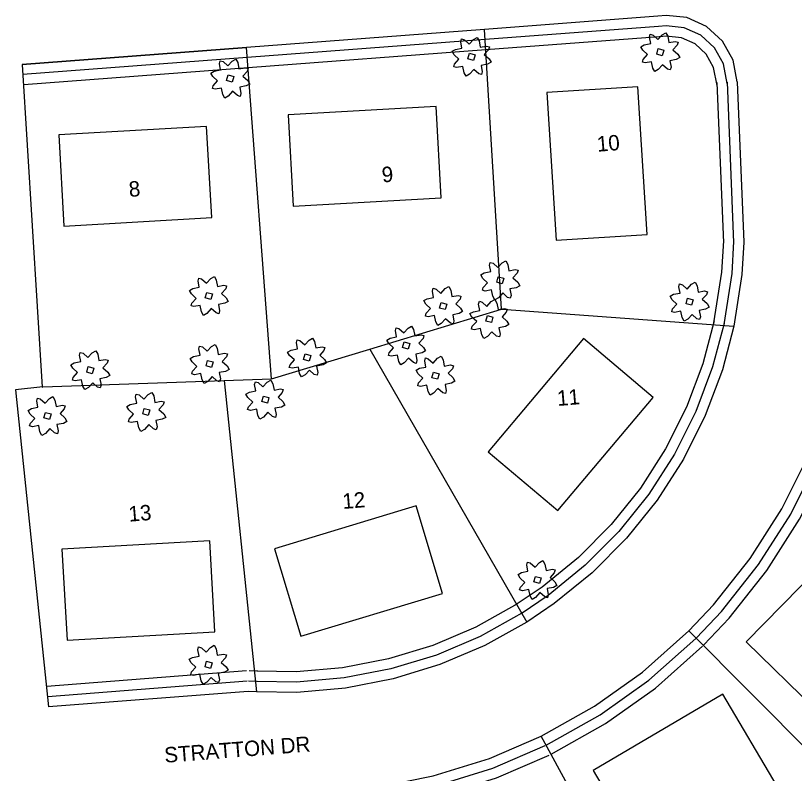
# Model space of a CAD drawing. Extents: x 1810019 to 1811399, y 1074962 to 1076105.
# Drawn here: x 1810244.4 to 1810548, y 1075531.7 to 1075827.1 of the extents above; entities that cross this region are included whole.
import ezdxf

# ---------------------------------------------------------------- set-up
doc = ezdxf.new("R2010")
doc.units = 0
for name, color, linetype in [('Environmental-New trees', 7, 'Continuous'), ('Property-Buildings', 7, 'Continuous'), ('Roadway-Land lines', 7, 'Continuous'), ('Roadway-Sidewalks', 7, 'Continuous'), ('Text-Property owner', 7, 'Continuous'), ('Text-Route label', 7, 'Continuous')]:
    doc.layers.add(name, color=color, linetype=linetype)

msp = doc.modelspace()

# ---------------------------------------------------------------- linework, layer by layer
at = {"layer": 'Environmental-New trees'}
for points in [[(1810488.71, 1075808.93), (1810489.02, 1075810.01), (1810490.71, 1075811.87), (1810488.85, 1075813.57), (1810488.07, 1075814.95), (1810489.43, 1075815.71), (1810491.93, 1075816.21), (1810491.46, 1075818.68), (1810491.76, 1075819.76), (1810492.85, 1075819.45), (1810494.71, 1075817.76), (1810496.4, 1075819.62), (1810497.79, 1075820.4), (1810498.57, 1075819.01), (1810499.04, 1075816.54), (1810501.51, 1075817.01), (1810502.6, 1075816.71), (1810502.23, 1075815.55), (1810500.6, 1075813.76), (1810502.46, 1075812.07), (1810503.24, 1075810.68), (1810501.88, 1075809.92), (1810499.38, 1075809.43), (1810499.85, 1075806.96), (1810499.54, 1075805.88), (1810498.46, 1075806.18), (1810496.6, 1075807.88), (1810494.91, 1075806.01), (1810493.52, 1075805.24), (1810492.74, 1075806.63), (1810492.27, 1075809.1), (1810489.8, 1075808.62)], [(1810415.17, 1075807.11), (1810415.47, 1075808.19), (1810417.16, 1075810.05), (1810415.3, 1075811.75), (1810414.52, 1075813.14), (1810415.88, 1075813.89), (1810418.38, 1075814.39), (1810417.91, 1075816.86), (1810418.22, 1075817.94), (1810419.3, 1075817.64), (1810421.16, 1075815.94), (1810422.85, 1075817.8), (1810424.24, 1075818.58), (1810425.02, 1075817.19), (1810425.49, 1075814.72), (1810427.96, 1075815.19), (1810429.05, 1075814.89), (1810428.68, 1075813.73), (1810427.05, 1075811.95), (1810428.91, 1075810.25), (1810429.69, 1075808.86), (1810428.34, 1075808.11), (1810425.83, 1075807.61), (1810426.3, 1075805.14), (1810426, 1075804.06), (1810424.91, 1075804.36), (1810423.05, 1075806.06), (1810421.36, 1075804.2), (1810419.97, 1075803.42), (1810419.19, 1075804.81), (1810418.72, 1075807.28), (1810416.25, 1075806.8)], [(1810494.88, 1075814.21), (1810497.04, 1075813.6), (1810496.43, 1075811.43), (1810494.27, 1075812.04)], [(1810321.09, 1075798.64), (1810321.4, 1075799.72), (1810323.09, 1075801.58), (1810321.23, 1075803.27), (1810320.45, 1075804.66), (1810321.81, 1075805.42), (1810324.31, 1075805.91), (1810323.84, 1075808.38), (1810324.15, 1075809.47), (1810325.23, 1075809.16), (1810327.09, 1075807.47), (1810328.78, 1075809.33), (1810330.17, 1075810.11), (1810330.95, 1075808.72), (1810331.42, 1075806.25), (1810333.89, 1075806.72), (1810334.98, 1075806.42), (1810334.61, 1075805.26), (1810332.98, 1075803.47), (1810334.84, 1075801.78), (1810335.62, 1075800.39), (1810334.27, 1075799.63), (1810331.76, 1075799.14), (1810332.23, 1075796.67), (1810331.93, 1075795.59), (1810330.84, 1075795.89), (1810328.98, 1075797.58), (1810327.29, 1075795.72), (1810325.9, 1075794.94), (1810325.12, 1075796.33), (1810324.65, 1075798.8), (1810322.18, 1075798.33)], [(1810421.33, 1075812.39), (1810423.49, 1075811.78), (1810422.88, 1075809.61), (1810420.72, 1075810.22)], [(1810327.26, 1075803.91), (1810329.42, 1075803.3), (1810328.81, 1075801.14), (1810326.65, 1075801.75)], [(1810426.37, 1075720.01), (1810426.67, 1075721.09), (1810428.37, 1075722.96), (1810426.5, 1075724.65), (1810425.73, 1075726.04), (1810427.08, 1075726.79), (1810429.59, 1075727.29), (1810429.11, 1075729.76), (1810429.42, 1075730.84), (1810430.5, 1075730.54), (1810432.36, 1075728.84), (1810434.06, 1075730.7), (1810435.44, 1075731.48), (1810436.22, 1075730.09), (1810436.7, 1075727.62), (1810439.17, 1075728.1), (1810440.25, 1075727.79), (1810439.88, 1075726.63), (1810438.25, 1075724.85), (1810440.11, 1075723.15), (1810440.89, 1075721.76), (1810439.54, 1075721.01), (1810437.03, 1075720.51), (1810437.5, 1075718.04), (1810437.2, 1075716.96), (1810436.12, 1075717.26), (1810434.25, 1075718.96), (1810432.56, 1075717.1), (1810431.17, 1075716.32), (1810430.39, 1075717.71), (1810429.92, 1075720.18), (1810427.45, 1075719.71)], [(1810312.77, 1075713.93), (1810313.07, 1075715.01), (1810314.77, 1075716.87), (1810312.91, 1075718.57), (1810312.13, 1075719.96), (1810313.48, 1075720.71), (1810315.99, 1075721.21), (1810315.52, 1075723.68), (1810315.82, 1075724.76), (1810316.9, 1075724.46), (1810318.77, 1075722.76), (1810320.46, 1075724.62), (1810321.85, 1075725.4), (1810322.62, 1075724.01), (1810323.1, 1075721.54), (1810325.57, 1075722.02), (1810326.65, 1075721.71), (1810326.28, 1075720.55), (1810324.65, 1075718.77), (1810326.51, 1075717.07), (1810327.29, 1075715.68), (1810325.94, 1075714.93), (1810323.43, 1075714.43), (1810323.91, 1075711.96), (1810323.6, 1075710.88), (1810322.52, 1075711.18), (1810320.66, 1075712.88), (1810318.96, 1075711.02), (1810317.57, 1075710.24), (1810316.8, 1075711.63), (1810316.32, 1075714.1), (1810313.85, 1075713.63)], [(1810432.53, 1075725.29), (1810434.7, 1075724.68), (1810434.09, 1075722.51), (1810431.92, 1075723.12)], [(1810500.16, 1075711.66), (1810500.46, 1075712.74), (1810502.16, 1075714.6), (1810500.29, 1075716.3), (1810499.52, 1075717.68), (1810500.87, 1075718.44), (1810503.38, 1075718.93), (1810502.9, 1075721.41), (1810503.21, 1075722.49), (1810504.29, 1075722.18), (1810506.15, 1075720.49), (1810507.85, 1075722.35), (1810509.23, 1075723.13), (1810510.01, 1075721.74), (1810510.49, 1075719.27), (1810512.96, 1075719.74), (1810514.04, 1075719.44), (1810513.67, 1075718.28), (1810512.04, 1075716.49), (1810513.9, 1075714.8), (1810514.68, 1075713.41), (1810513.33, 1075712.65), (1810510.82, 1075712.16), (1810511.29, 1075709.69), (1810510.99, 1075708.61), (1810509.91, 1075708.91), (1810508.04, 1075710.6), (1810506.35, 1075708.74), (1810504.96, 1075707.97), (1810504.18, 1075709.35), (1810503.71, 1075711.83), (1810501.24, 1075711.35)], [(1810318.93, 1075719.21), (1810321.1, 1075718.6), (1810320.49, 1075716.43), (1810318.32, 1075717.04)], [(1810404.11, 1075709.96), (1810404.42, 1075711.04), (1810406.11, 1075712.9), (1810404.25, 1075714.6), (1810403.47, 1075715.99), (1810404.82, 1075716.74), (1810407.33, 1075717.24), (1810406.86, 1075719.71), (1810407.16, 1075720.79), (1810408.25, 1075720.49), (1810410.11, 1075718.79), (1810411.8, 1075720.65), (1810413.19, 1075721.43), (1810413.97, 1075720.04), (1810414.44, 1075717.57), (1810416.91, 1075718.04), (1810417.99, 1075717.74), (1810417.62, 1075716.58), (1810415.99, 1075714.79), (1810417.86, 1075713.1), (1810418.63, 1075711.71), (1810417.28, 1075710.96), (1810414.77, 1075710.46), (1810415.25, 1075707.99), (1810414.94, 1075706.91), (1810413.86, 1075707.21), (1810412, 1075708.91), (1810410.3, 1075707.05), (1810408.92, 1075706.27), (1810408.14, 1075707.66), (1810407.67, 1075710.13), (1810405.19, 1075709.65)], [(1810422.11, 1075704.89), (1810422.41, 1075705.97), (1810424.11, 1075707.83), (1810422.24, 1075709.53), (1810421.47, 1075710.91), (1810422.82, 1075711.67), (1810425.33, 1075712.17), (1810424.85, 1075714.64), (1810425.16, 1075715.72), (1810426.24, 1075715.42), (1810428.1, 1075713.72), (1810429.8, 1075715.58), (1810431.18, 1075716.36), (1810431.96, 1075714.97), (1810432.43, 1075712.5), (1810434.91, 1075712.97), (1810435.99, 1075712.67), (1810435.62, 1075711.51), (1810433.99, 1075709.72), (1810435.85, 1075708.03), (1810436.63, 1075706.64), (1810435.28, 1075705.89), (1810432.77, 1075705.39), (1810433.24, 1075702.92), (1810432.94, 1075701.84), (1810431.85, 1075702.14), (1810429.99, 1075703.84), (1810428.3, 1075701.98), (1810426.91, 1075701.2), (1810426.13, 1075702.59), (1810425.66, 1075705.06), (1810423.19, 1075704.58)], [(1810506.32, 1075716.94), (1810508.49, 1075716.33), (1810507.88, 1075714.16), (1810505.71, 1075714.77)], [(1810410.27, 1075715.24), (1810412.44, 1075714.63), (1810411.83, 1075712.46), (1810409.66, 1075713.07)], [(1810428.27, 1075710.17), (1810430.44, 1075709.56), (1810429.83, 1075707.39), (1810427.66, 1075708)], [(1810389.68, 1075694.59), (1810389.99, 1075695.68), (1810391.68, 1075697.54), (1810389.82, 1075699.23), (1810389.04, 1075700.62), (1810390.39, 1075701.38), (1810392.9, 1075701.87), (1810392.43, 1075704.34), (1810392.73, 1075705.42), (1810393.82, 1075705.12), (1810395.68, 1075703.43), (1810397.37, 1075705.29), (1810398.76, 1075706.06), (1810399.54, 1075704.68), (1810400.01, 1075702.21), (1810402.48, 1075702.68), (1810403.56, 1075702.37), (1810403.19, 1075701.22), (1810401.56, 1075699.43), (1810403.43, 1075697.74), (1810404.2, 1075696.35), (1810402.85, 1075695.59), (1810400.34, 1075695.1), (1810400.82, 1075692.63), (1810400.51, 1075691.54), (1810399.43, 1075691.85), (1810397.57, 1075693.54), (1810395.87, 1075691.68), (1810394.49, 1075690.9), (1810393.71, 1075692.29), (1810393.24, 1075694.76), (1810390.76, 1075694.29)], [(1810351.07, 1075689.93), (1810351.38, 1075691.01), (1810353.07, 1075692.87), (1810351.21, 1075694.56), (1810350.43, 1075695.95), (1810351.78, 1075696.71), (1810354.29, 1075697.2), (1810353.82, 1075699.67), (1810354.12, 1075700.76), (1810355.21, 1075700.45), (1810357.07, 1075698.76), (1810358.76, 1075700.62), (1810360.15, 1075701.4), (1810360.93, 1075700.01), (1810361.4, 1075697.54), (1810363.87, 1075698.01), (1810364.95, 1075697.71), (1810364.58, 1075696.55), (1810362.96, 1075694.76), (1810364.82, 1075693.07), (1810365.59, 1075691.68), (1810364.24, 1075690.92), (1810361.73, 1075690.43), (1810362.21, 1075687.96), (1810361.9, 1075686.87), (1810360.82, 1075687.18), (1810358.96, 1075688.87), (1810357.26, 1075687.01), (1810355.88, 1075686.23), (1810355.1, 1075687.62), (1810354.63, 1075690.09), (1810352.15, 1075689.62)], [(1810313.07, 1075687.42), (1810313.38, 1075688.5), (1810315.07, 1075690.36), (1810313.21, 1075692.06), (1810312.43, 1075693.45), (1810313.78, 1075694.2), (1810316.29, 1075694.7), (1810315.82, 1075697.17), (1810316.12, 1075698.25), (1810317.2, 1075697.95), (1810319.07, 1075696.25), (1810320.76, 1075698.11), (1810322.15, 1075698.89), (1810322.93, 1075697.5), (1810323.4, 1075695.03), (1810325.87, 1075695.5), (1810326.95, 1075695.2), (1810326.58, 1075694.04), (1810324.95, 1075692.25), (1810326.82, 1075690.56), (1810327.59, 1075689.17), (1810326.24, 1075688.42), (1810323.73, 1075687.92), (1810324.21, 1075685.45), (1810323.9, 1075684.37), (1810322.82, 1075684.67), (1810320.96, 1075686.37), (1810319.26, 1075684.51), (1810317.88, 1075683.73), (1810317.1, 1075685.12), (1810316.62, 1075687.59), (1810314.15, 1075687.11)], [(1810395.84, 1075699.87), (1810398.01, 1075699.26), (1810397.4, 1075697.09), (1810395.23, 1075697.71)], [(1810266.54, 1075684.98), (1810266.85, 1075686.07), (1810268.54, 1075687.93), (1810266.68, 1075689.62), (1810265.9, 1075691.01), (1810267.25, 1075691.77), (1810269.76, 1075692.26), (1810269.29, 1075694.73), (1810269.59, 1075695.81), (1810270.68, 1075695.51), (1810272.54, 1075693.82), (1810274.23, 1075695.68), (1810275.62, 1075696.45), (1810276.4, 1075695.07), (1810276.87, 1075692.6), (1810279.34, 1075693.07), (1810280.42, 1075692.76), (1810280.06, 1075691.61), (1810278.43, 1075689.82), (1810280.29, 1075688.13), (1810281.06, 1075686.74), (1810279.71, 1075685.98), (1810277.21, 1075685.49), (1810277.68, 1075683.01), (1810277.37, 1075681.93), (1810276.29, 1075682.24), (1810274.43, 1075683.93), (1810272.74, 1075682.07), (1810271.35, 1075681.29), (1810270.57, 1075682.68), (1810270.1, 1075685.15), (1810267.63, 1075684.68)], [(1810357.23, 1075695.2), (1810359.4, 1075694.59), (1810358.79, 1075692.43), (1810356.62, 1075693.04)], [(1810401.13, 1075682.82), (1810401.43, 1075683.9), (1810403.12, 1075685.76), (1810401.26, 1075687.46), (1810400.49, 1075688.84), (1810401.84, 1075689.6), (1810404.35, 1075690.1), (1810403.87, 1075692.57), (1810404.18, 1075693.65), (1810405.26, 1075693.35), (1810407.12, 1075691.65), (1810408.82, 1075693.51), (1810410.2, 1075694.29), (1810410.98, 1075692.9), (1810411.45, 1075690.43), (1810413.93, 1075690.9), (1810415.01, 1075690.6), (1810414.64, 1075689.44), (1810413.01, 1075687.65), (1810414.87, 1075685.96), (1810415.65, 1075684.57), (1810414.3, 1075683.82), (1810411.79, 1075683.32), (1810412.26, 1075680.85), (1810411.96, 1075679.77), (1810410.87, 1075680.07), (1810409.01, 1075681.77), (1810407.32, 1075679.91), (1810405.93, 1075679.13), (1810405.15, 1075680.52), (1810404.68, 1075682.99), (1810402.21, 1075682.51)], [(1810319.23, 1075692.7), (1810321.4, 1075692.09), (1810320.79, 1075689.92), (1810318.62, 1075690.53)], [(1810272.71, 1075690.26), (1810274.87, 1075689.65), (1810274.26, 1075687.48), (1810272.1, 1075688.09)], [(1810407.29, 1075688.1), (1810409.46, 1075687.49), (1810408.85, 1075685.32), (1810406.68, 1075685.93)], [(1810334.8, 1075673.53), (1810335.1, 1075674.61), (1810336.79, 1075676.47), (1810334.93, 1075678.16), (1810334.16, 1075679.55), (1810335.51, 1075680.31), (1810338.02, 1075680.8), (1810337.54, 1075683.27), (1810337.85, 1075684.36), (1810338.93, 1075684.05), (1810340.79, 1075682.36), (1810342.49, 1075684.22), (1810343.87, 1075685), (1810344.65, 1075683.61), (1810345.12, 1075681.14), (1810347.6, 1075681.61), (1810348.68, 1075681.31), (1810348.31, 1075680.15), (1810346.68, 1075678.36), (1810348.54, 1075676.67), (1810349.32, 1075675.28), (1810347.97, 1075674.52), (1810345.46, 1075674.03), (1810345.93, 1075671.56), (1810345.63, 1075670.47), (1810344.54, 1075670.78), (1810342.68, 1075672.47), (1810340.99, 1075670.61), (1810339.6, 1075669.83), (1810338.82, 1075671.22), (1810338.35, 1075673.69), (1810335.88, 1075673.22)], [(1810288.38, 1075668.73), (1810288.68, 1075669.81), (1810290.38, 1075671.67), (1810288.52, 1075673.36), (1810287.74, 1075674.75), (1810289.09, 1075675.51), (1810291.6, 1075676), (1810291.13, 1075678.47), (1810291.43, 1075679.56), (1810292.51, 1075679.25), (1810294.37, 1075677.56), (1810296.07, 1075679.42), (1810297.46, 1075680.2), (1810298.23, 1075678.81), (1810298.71, 1075676.34), (1810301.18, 1075676.81), (1810302.26, 1075676.51), (1810301.89, 1075675.35), (1810300.26, 1075673.56), (1810302.12, 1075671.87), (1810302.9, 1075670.48), (1810301.55, 1075669.72), (1810299.04, 1075669.23), (1810299.52, 1075666.76), (1810299.21, 1075665.67), (1810298.13, 1075665.98), (1810296.27, 1075667.67), (1810294.57, 1075665.81), (1810293.18, 1075665.03), (1810292.41, 1075666.42), (1810291.93, 1075668.89), (1810289.46, 1075668.42)], [(1810249.86, 1075667.14), (1810250.17, 1075668.23), (1810251.86, 1075670.09), (1810250, 1075671.78), (1810249.22, 1075673.17), (1810250.57, 1075673.93), (1810253.08, 1075674.42), (1810252.61, 1075676.89), (1810252.91, 1075677.97), (1810254, 1075677.67), (1810255.86, 1075675.98), (1810257.55, 1075677.84), (1810258.94, 1075678.61), (1810259.72, 1075677.23), (1810260.19, 1075674.75), (1810262.66, 1075675.23), (1810263.74, 1075674.92), (1810263.37, 1075673.77), (1810261.75, 1075671.98), (1810263.61, 1075670.28), (1810264.38, 1075668.9), (1810263.03, 1075668.14), (1810260.52, 1075667.65), (1810261, 1075665.17), (1810260.69, 1075664.09), (1810259.61, 1075664.4), (1810257.75, 1075666.09), (1810256.05, 1075664.23), (1810254.67, 1075663.45), (1810253.89, 1075664.84), (1810253.42, 1075667.31), (1810250.94, 1075666.84)], [(1810340.96, 1075678.8), (1810343.13, 1075678.19), (1810342.52, 1075676.03), (1810340.35, 1075676.64)], [(1810294.54, 1075674), (1810296.71, 1075673.39), (1810296.1, 1075671.23), (1810293.93, 1075671.84)], [(1810256.02, 1075672.42), (1810258.19, 1075671.81), (1810257.58, 1075669.64), (1810255.41, 1075670.25)], [(1810440.86, 1075603.23), (1810441.17, 1075604.31), (1810442.86, 1075606.17), (1810441, 1075607.86), (1810440.22, 1075609.25), (1810441.57, 1075610.01), (1810444.08, 1075610.5), (1810443.61, 1075612.97), (1810443.91, 1075614.06), (1810444.99, 1075613.75), (1810446.86, 1075612.06), (1810448.55, 1075613.92), (1810449.94, 1075614.7), (1810450.72, 1075613.31), (1810451.19, 1075610.84), (1810453.66, 1075611.31), (1810454.74, 1075611.01), (1810454.37, 1075609.85), (1810452.74, 1075608.06), (1810454.61, 1075606.37), (1810455.38, 1075604.98), (1810454.03, 1075604.22), (1810451.52, 1075603.73), (1810452, 1075601.26), (1810451.69, 1075600.18), (1810450.61, 1075600.48), (1810448.75, 1075602.17), (1810447.05, 1075600.31), (1810445.67, 1075599.53), (1810444.89, 1075600.92), (1810444.41, 1075603.39), (1810441.94, 1075602.92)], [(1810447.02, 1075608.5), (1810449.19, 1075607.89), (1810448.58, 1075605.73), (1810446.41, 1075606.34)], [(1810312.67, 1075570.17), (1810312.97, 1075571.25), (1810314.67, 1075573.11), (1810312.81, 1075574.81), (1810312.03, 1075576.19), (1810313.38, 1075576.95), (1810315.89, 1075577.44), (1810315.42, 1075579.92), (1810315.72, 1075581), (1810316.8, 1075580.69), (1810318.66, 1075579), (1810320.36, 1075580.86), (1810321.75, 1075581.64), (1810322.52, 1075580.25), (1810323, 1075577.78), (1810325.47, 1075578.25), (1810326.55, 1075577.95), (1810326.18, 1075576.79), (1810324.55, 1075575), (1810326.41, 1075573.31), (1810327.19, 1075571.92), (1810325.84, 1075571.16), (1810323.33, 1075570.67), (1810323.81, 1075568.2), (1810323.5, 1075567.12), (1810322.42, 1075567.42), (1810320.56, 1075569.11), (1810318.86, 1075567.25), (1810317.47, 1075566.48), (1810316.7, 1075567.86), (1810316.22, 1075570.34), (1810313.75, 1075569.86)], [(1810318.83, 1075575.45), (1810321, 1075574.84), (1810320.39, 1075572.67), (1810318.22, 1075573.28)]]:
    msp.add_lwpolyline(points, close=True, dxfattribs=at)
at = {"layer": 'Property-Buildings'}
for points in [[(1810490.62, 1075741.77), (1810486.91, 1075799.36), (1810451.4, 1075797.07), (1810455.12, 1075739.48)], [(1810352.64, 1075752.83), (1810410.26, 1075756.08), (1810408.25, 1075791.6), (1810350.63, 1075788.35)], [(1810263.2, 1075745.06), (1810320.82, 1075748.31), (1810318.81, 1075783.83), (1810261.19, 1075780.58)], [(1810455.75, 1075634.15), (1810492.95, 1075678.28), (1810465.74, 1075701.21), (1810428.55, 1075657.08)], [(1810355.58, 1075585.17), (1810410.81, 1075601.9), (1810400.5, 1075635.95), (1810345.27, 1075619.22)], [(1810529.21, 1075583.03), (1810556.02, 1075556.72), (1810597.9, 1075599.4), (1810571.1, 1075625.71)], [(1810264.43, 1075583.6), (1810322.05, 1075586.85), (1810320.04, 1075622.37), (1810262.42, 1075619.12)], [(1810469.57, 1075532.8), (1810490.73, 1075496.96), (1810541.25, 1075526.79), (1810520.08, 1075562.63)]]:
    msp.add_lwpolyline(points, close=True, dxfattribs=at)
at = {"layer": 'Roadway-Land lines'}
for p, q in [((1810494.7, 1075826.79), (1810427.13, 1075821.68)), ((1810427.13, 1075821.68), (1810334.37, 1075814.67)), ((1810433.79, 1075712.64), (1810427.13, 1075821.68)), ((1810246.94, 1075808.06), (1810334.37, 1075814.67)), ((1810334.37, 1075814.67), (1810246.94, 1075808.06)), ((1810344.14, 1075685.5), (1810334.37, 1075814.67)), ((1810246.94, 1075808.06), (1810254.71, 1075682.31)), ((1810525.68, 1075801.3), (1810528.25, 1075738.82)), ((1810382.41, 1075697.09), (1810433.79, 1075712.64)), ((1810433.79, 1075712.64), (1810434, 1075712.71)), ((1810434, 1075712.71), (1810524.38, 1075706.08)), ((1810344.14, 1075685.5), (1810382.41, 1075697.09)), ((1810382.41, 1075697.09), (1810443.66, 1075590.65)), ((1810325.73, 1075684.84), (1810344.14, 1075685.5)), ((1810254.95, 1075682.32), (1810244.37, 1075681.25)), ((1810254.71, 1075682.31), (1810254.95, 1075682.32)), ((1810254.95, 1075682.32), (1810325.73, 1075684.84)), ((1810325.73, 1075684.84), (1810338.32, 1075563.52)), ((1810244.37, 1075681.25), (1810257.23, 1075557.62)), ((1810626.09, 1075467.25), (1810506.83, 1075587.28)), ((1810335, 1075563.7), (1810257.23, 1075557.62)), ((1810338.32, 1075563.52), (1810335, 1075563.7)), ((1810524.22, 1075409.88), (1810449.23, 1075546.24))]:
    msp.add_line(p, q, dxfattribs=at)
for points in [[(1810525.68, 1075801.3), (1810524.1, 1075809.64), (1810519.97, 1075817.06), (1810513.72, 1075822.8), (1810505.97, 1075826.27), (1810498.02, 1075827.07), (1810494.7, 1075826.79)], [(1810528.25, 1075738.82), (1810527.48, 1075726.17), (1810524.38, 1075706.08)], [(1810524.38, 1075706.08), (1810519.89, 1075688.97), (1810513.19, 1075671.18), (1810504.67, 1075654.2), (1810494.4, 1075638.2), (1810482.5, 1075623.38), (1810469.11, 1075609.89), (1810454.37, 1075597.89), (1810443.66, 1075590.65)], [(1810506.83, 1075587.28), (1810516.47, 1075597.47), (1810530.73, 1075615.43), (1810543.02, 1075634.79), (1810551.82, 1075652.29)], [(1810443.66, 1075590.65), (1810427.27, 1075581.54), (1810409.78, 1075574.11), (1810391.6, 1075568.55), (1810372.94, 1075564.94), (1810354, 1075563.32), (1810338.32, 1075563.52)], [(1810449.23, 1075546.24), (1810470.08, 1075557.9), (1810488.77, 1075571.19), (1810506.83, 1075587.28)], [(1810373.22, 1075524.98), (1810384.67, 1075526.29), (1810407.16, 1075530.76), (1810429.05, 1075537.57), (1810449.23, 1075546.24)]]:
    msp.add_lwpolyline(points, dxfattribs=at)
at = {"layer": 'Roadway-Sidewalks'}
for p, q in [((1810495, 1075822.8), (1810427.43, 1075817.69)), ((1810495.3, 1075818.81), (1810427.73, 1075813.7)), ((1810427.43, 1075817.69), (1810334.68, 1075810.68)), ((1810427.73, 1075813.7), (1810334.98, 1075806.69)), ((1810334.68, 1075810.68), (1810247.24, 1075804.07)), ((1810334.98, 1075806.69), (1810247.54, 1075800.08)), ((1810517.68, 1075800.98), (1810520.26, 1075738.49)), ((1810521.68, 1075801.14), (1810524.25, 1075738.65)), ((1810334.37, 1075571.68), (1810256.6, 1075565.6)), ((1810338.76, 1075571.51), (1810335.44, 1075571.69)), ((1810334.69, 1075567.69), (1810256.92, 1075561.61)), ((1810338.54, 1075567.51), (1810335.22, 1075567.7))]:
    msp.add_line(p, q, dxfattribs=at)
for points in [[(1810521.75, 1075800.56), (1810520.29, 1075808.27), (1810516.79, 1075814.55), (1810511.49, 1075819.41), (1810504.92, 1075822.35), (1810497.99, 1075823.05), (1810495.03, 1075822.8)], [(1810517.82, 1075799.82), (1810516.48, 1075806.89), (1810513.61, 1075812.04), (1810509.26, 1075816.03), (1810503.88, 1075818.44), (1810497.96, 1075819.03), (1810495.36, 1075818.82)], [(1810520.27, 1075739.3), (1810519.52, 1075727.02), (1810516.47, 1075707.3)], [(1810524.26, 1075739.06), (1810523.5, 1075726.59), (1810520.43, 1075706.69)], [(1810516.64, 1075708.11), (1810512.25, 1075691.4), (1810505.86, 1075674.4), (1810497.71, 1075658.16), (1810487.9, 1075642.88), (1810476.53, 1075628.72), (1810463.73, 1075615.83), (1810449.6, 1075604.32), (1810439.17, 1075597.27)], [(1810520.51, 1075707.1), (1810516.07, 1075690.19), (1810509.53, 1075672.79), (1810501.19, 1075656.18), (1810491.15, 1075640.54), (1810479.52, 1075626.05), (1810466.42, 1075612.86), (1810451.98, 1075601.1), (1810441.42, 1075593.96)], [(1810509.74, 1075584.53), (1810519.5, 1075594.85), (1810534, 1075613.11), (1810546.5, 1075632.81), (1810555.4, 1075650.49)], [(1810512.65, 1075581.78), (1810522.52, 1075592.23), (1810537.26, 1075610.78), (1810549.99, 1075630.84), (1810558.97, 1075648.69)], [(1810439.77, 1075597.64), (1810423.75, 1075588.74), (1810407.04, 1075581.63), (1810389.67, 1075576.33), (1810371.83, 1075572.88), (1810353.71, 1075571.33), (1810338.42, 1075571.52)], [(1810441.71, 1075594.14), (1810425.51, 1075585.14), (1810408.41, 1075577.87), (1810390.63, 1075572.44), (1810372.39, 1075568.91), (1810353.85, 1075567.32), (1810338.37, 1075567.52)], [(1810451.18, 1075542.75), (1810472.23, 1075554.52), (1810491.27, 1075568.06), (1810509.49, 1075584.29)], [(1810453.14, 1075539.26), (1810474.37, 1075551.13), (1810493.76, 1075564.93), (1810512.15, 1075581.3)], [(1810373.68, 1075521.01), (1810385.28, 1075522.34), (1810408.14, 1075526.88), (1810430.44, 1075533.82), (1810450.81, 1075542.57)], [(1810374.13, 1075517.03), (1810385.9, 1075518.38), (1810409.13, 1075523), (1810431.82, 1075530.06), (1810452.39, 1075538.89)]]:
    msp.add_lwpolyline(points, dxfattribs=at)

# ---------------------------------------------------------------- texts
at = {"layer": 'Text-Property owner'}
for s, p in [('10', (1810471.19, 1075773.98)), ('9', (1810387.35, 1075762.02)), ('8', (1810288.74, 1075756.37)), ('11', (1810455.67, 1075674.91)), ('12', (1810371.99, 1075634.77)), ('13', (1810288.63, 1075629.81))]:
    msp.add_text(s, height=6, rotation=4.6517, dxfattribs=at).set_placement(p)
at = {"layer": 'Text-Route label'}
msp.add_text('STRATTON DR', height=6, rotation=4.452, dxfattribs=at).set_placement((1810302.58, 1075535.85))

doc.saveas('drawing.dxf')
